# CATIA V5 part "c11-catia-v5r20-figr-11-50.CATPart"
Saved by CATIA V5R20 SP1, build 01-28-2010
Part number: Part1
Bounding box of the stored display mesh (mm): x -49.998 to 49.998, y -70 to 70, z 0 to 80.773
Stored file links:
  D:\v5_r20\psrt_files_downloaded\c11\c11-catia-v5r20-figr-11-50.CATPart
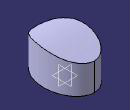
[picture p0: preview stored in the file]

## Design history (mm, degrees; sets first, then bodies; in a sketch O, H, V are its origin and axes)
Set1
  Extrude1: Element1 Sketch2, Lim1 82, Lim2 70, Direction yz-plane
Body1 (main body)
  Sketch1 on xy-plane, origin (0, 0, 0), H (1, 0, 0), V (0, 1, 0)
    ellipse A1 centre (0, 0) semi-axes 70, 50 rotation 90
    point P1 (50, 0)
    coincidence: P1 H, A1 P1
  Pad1: profile Sketch1, direction (0, 0, 1), length 84
  Split1: SplitPlane Extrude1
  Sketch2 on yz-plane, origin (0, 0, 0), H (0, 1, 0), V (0, 0, 1)
    spline S1 through (-90, 50) (-30, 80) (50, 70) (90, 60)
